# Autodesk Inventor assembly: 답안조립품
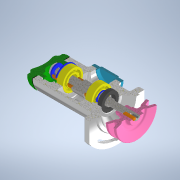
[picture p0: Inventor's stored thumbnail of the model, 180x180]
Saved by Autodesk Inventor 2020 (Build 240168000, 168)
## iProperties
Created: 2022-05
Part Number: 답안조립품
Document SubType Name: Assembly
Designer: Student
Author: Student
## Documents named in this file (17)
- C:\Users\Student\Desktop\720506V1018\답안조립품.iam
- C:\Users\Student\Desktop\720506V1018\본체.ipt
- C:\Users\Student\Desktop\720506V1018\탑 커버.ipt
- C:\Users\Student\Desktop\720506V1018\사이드 커버.ipt
- 사이드 커버.ipt
- C:\Users\Student\Desktop\720506V1018\개스킷.ipt
- C:\Users\Student\Desktop\720506V1018\베어링 6202.ipt
- C:\Users\Student\Desktop\720506V1018\멈춤링 35 x 1.6.ipt
- C:\Users\Student\Desktop\720506V1018\축.ipt
- C:\Users\Student\Desktop\720506V1018\부시1.ipt
- C:\Users\Student\Desktop\720506V1018\멈춤링 15 x 1.ipt
- C:\Users\Student\Desktop\720506V1018\오일 실 15 x 30 x 7.ipt
- C:\Users\Student\Desktop\720506V1018\키 4 x 4.ipt
- C:\Users\Student\Desktop\720506V1018\너트 M10.ipt
- C:\Users\Student\Desktop\720506V1018\부시2.ipt
- C:\Users\Student\Desktop\720506V1018\와셔 10 x 21.ipt
- C:\Users\Student\Desktop\720506V1018\V-벨트풀리.ipt
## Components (2 placed, 2 different names)
1. 개스킷:1
2. V-벨트풀리:1
